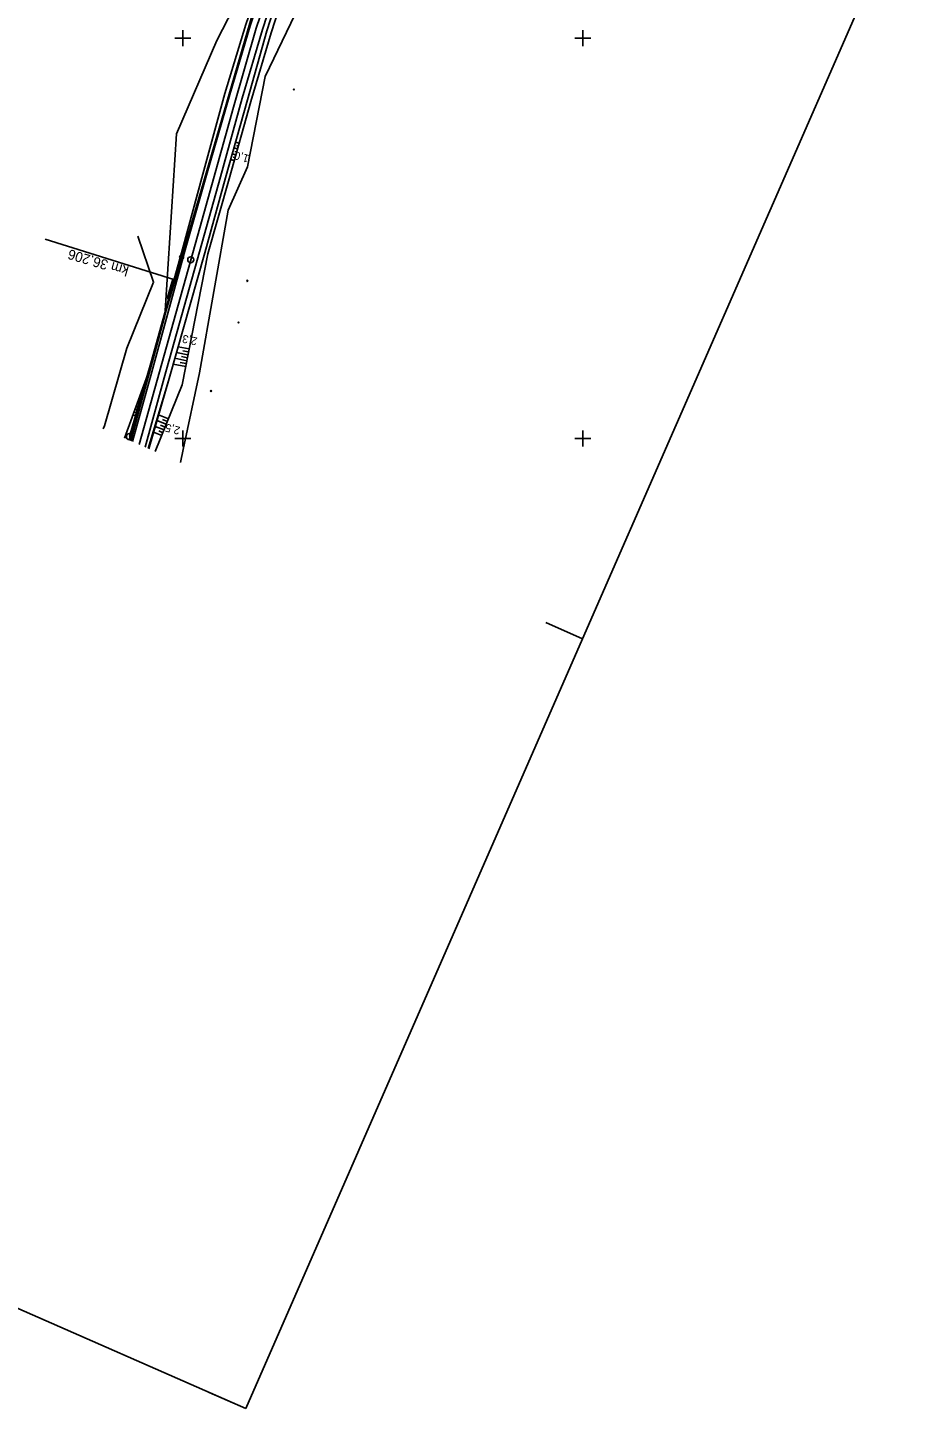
# Model space of a CAD drawing. Extents: x -806856 to -806332, y -1151642 to -1150946.
# Drawn here: x -806638.8 to -806415.8, y -1151642.4 to -1151297.3 of the extents above; entities that cross this region are included whole.
import ezdxf

# ---------------------------------------------------------------- set-up
doc = ezdxf.new("R2010")
doc.units = 0
for name, color, linetype in [('0381KM032-037P - Vrstva 1', 7, 'Continuous'), ('0381KM032-037P - Vrstva 17', 7, 'Continuous'), ('0381KM032-037P - Vrstva 4', 7, 'Continuous'), ('0381KM032-037P - Vrstva 48', 7, 'Continuous'), ('0381KM032-037P - Vrstva 49', 7, 'Continuous'), ('0381KM032-037P - Vrstva 7', 7, 'Continuous'), ('0381KM032-037P - Vrstva 9', 7, 'Continuous'), ('formát', 7, 'Continuous'), ('hran DP - hran DP', 7, 'Continuous'), ('krizky_1000 - Vrstva 1', 7, 'Continuous'), ('vyt_sit - polygon', 7, 'Continuous'), ('vyt_sit - stávající', 7, 'Continuous')]:
    doc.layers.add(name, color=color, linetype=linetype)

msp = doc.modelspace()

# ---------------------------------------------------------------- linework, layer by layer
at = {"layer": '0381KM032-037P - Vrstva 1'}
for points in [[(-806575.26, -1151278.66), (-806581.61, -1151297.45), (-806587.32, -1151317.2)], [(-806587.32, -1151317.2), (-806595.77, -1151347.36), (-806604.1, -1151377.15), (-806610.94, -1151401.52)]]:
    msp.add_lwpolyline(points, dxfattribs=at)
at = {"layer": '0381KM032-037P - Vrstva 17'}
msp.add_lwpolyline([(-806611.24, -1151349.41), (-806607.31, -1151360.99), (-806614.01, -1151377.45), (-806619.53, -1151396.86), (-806619.89, -1151397.6)], dxfattribs=at)
at = {"layer": '0381KM032-037P - Vrstva 4'}
for points in [[(-806534.73, -1151198.81), (-806545.37, -1151216.39), (-806553.18, -1151229.13), (-806561.58, -1151243.53), (-806567.96, -1151255.6), (-806574.3, -1151269.24), (-806578.76, -1151280.27), (-806579.4, -1151282.54), (-806584.22, -1151296.56), (-806589.48, -1151313.82), (-806594.95, -1151333.92), (-806600.1, -1151352.67), (-806608.81, -1151384.22), (-806613.08, -1151400.58)], [(-806534.14, -1151199.19), (-806544.55, -1151216.75), (-806552.31, -1151229.7), (-806560.71, -1151244.03), (-806567.24, -1151256.24), (-806573.52, -1151269.73), (-806577.97, -1151280.92), (-806578.5, -1151282.67), (-806583.15, -1151296.86), (-806588.26, -1151314.07), (-806594.08, -1151334.22), (-806599.38, -1151352.89), (-806608.02, -1151384.26), (-806612.6, -1151400.79)], [(-806531.11, -1151200.55), (-806541.48, -1151217.8), (-806549.08, -1151230.92), (-806557.69, -1151245.47), (-806564.05, -1151257.36), (-806570.21, -1151270.63), (-806574.62, -1151281.75), (-806575.45, -1151283.67), (-806580.1, -1151297.77), (-806585.12, -1151314.97), (-806590.56, -1151334.63), (-806595.8, -1151353.37), (-806604.61, -1151384.9), (-806609.41, -1151402.19)], [(-806530.22, -1151201.05), (-806540.66, -1151218.65), (-806548.31, -1151231.35), (-806556.78, -1151246.08), (-806563.07, -1151257.89), (-806569.22, -1151271.02), (-806574.1, -1151282.08), (-806574.48, -1151284.1), (-806578.97, -1151298.16), (-806583.83, -1151315.38), (-806589.34, -1151334.88), (-806594.45, -1151353.63), (-806603.42, -1151385.04), (-806608.69, -1151402.5)]]:
    msp.add_lwpolyline(points, dxfattribs=at)
at = {"layer": '0381KM032-037P - Vrstva 48'}
for p, q in [((-806585.91, -1151326.21), (-806586.82, -1151325.96)), ((-806586.11, -1151326.94), (-806586.57, -1151326.81)), ((-806587.11, -1151330.55), (-806588.04, -1151330.29)), ((-806586.71, -1151329.1), (-806587.63, -1151328.85)), ((-806586.91, -1151329.82), (-806587.38, -1151329.7)), ((-806586.31, -1151327.66), (-806587.23, -1151327.4)), ((-806586.51, -1151328.38), (-806586.97, -1151328.25)), ((-806598.69, -1151379.1), (-806601.56, -1151378.53)), ((-806598.39, -1151377.63), (-806601.15, -1151377.08)), ((-806598.54, -1151378.36), (-806599.95, -1151378.08)), ((-806599.27, -1151382.04), (-806602.39, -1151381.42)), ((-806598.98, -1151380.57), (-806601.97, -1151379.98)), ((-806599.12, -1151381.31), (-806600.65, -1151381)), ((-806598.83, -1151379.83), (-806600.3, -1151379.54)), ((-806611.67, -1151391.97), (-806611.36, -1151392.08)), ((-806611.41, -1151391.27), (-806610.85, -1151391.47)), ((-806611.15, -1151390.56), (-806610.9, -1151390.65)), ((-806610.89, -1151389.86), (-806610.44, -1151390.02)), ((-806612.45, -1151394.08), (-806611.67, -1151394.37)), ((-806612.19, -1151393.38), (-806611.83, -1151393.51)), ((-806611.93, -1151392.67), (-806611.26, -1151392.92)), ((-806604.12, -1151396.48), (-806606.45, -1151395.55)), ((-806603.57, -1151395.08), (-806606.03, -1151394.1)), ((-806603.85, -1151395.78), (-806605.04, -1151395.3)), ((-806605.24, -1151399.26), (-806607.28, -1151398.45)), ((-806604.68, -1151397.87), (-806606.87, -1151397)), ((-806604.96, -1151398.57), (-806606.02, -1151398.14)), ((-806604.4, -1151397.17), (-806605.53, -1151396.72))]:
    msp.add_line(p, q, dxfattribs=at)
at = {"layer": '0381KM032-037P - Vrstva 49'}
for p, q in [((-806572.06, -1151312.59), (-806572.42, -1151312.95)), ((-806572.42, -1151312.59), (-806572.06, -1151312.95)), ((-806583.68, -1151360.44), (-806584.03, -1151360.8)), ((-806584.03, -1151360.44), (-806583.68, -1151360.8)), ((-806585.91, -1151370.83), (-806586.27, -1151371.18)), ((-806586.27, -1151370.83), (-806585.91, -1151371.18)), ((-806608.81, -1151384.22), (-806613.38, -1151400.45)), ((-806608.81, -1151384.22), (-806613.08, -1151400.58)), ((-806592.76, -1151387.98), (-806593.11, -1151388.33)), ((-806593.11, -1151387.98), (-806592.75, -1151388.33))]:
    msp.add_line(p, q, dxfattribs=at)
for points in [[(-806520.01, -1151188.39), (-806536.66, -1151214.61), (-806549.93, -1151238.4), (-806571.09, -1151278.57), (-806574.7, -1151288.79), (-806577.92, -1151298.67), (-806582.99, -1151315.77), (-806588.39, -1151335.12), (-806593.7, -1151353.88), (-806600.16, -1151386.57)], [(-806535.85, -1151198.12), (-806546.61, -1151215.57), (-806553.18, -1151229.13), (-806561.58, -1151243.53), (-806567.96, -1151255.6), (-806574.3, -1151269.24), (-806578.76, -1151280.27), (-806579.4, -1151282.54), (-806584.22, -1151296.56), (-806589.48, -1151313.82), (-806594.95, -1151333.92), (-806600.1, -1151352.67), (-806608.81, -1151384.22), (-806614.6, -1151399.91)], [(-806574.1, -1151282.08), (-806574.48, -1151284.1), (-806578.97, -1151298.16), (-806583.83, -1151315.38), (-806589.34, -1151334.88), (-806594.45, -1151353.63), (-806603.42, -1151385.04), (-806608.48, -1151402.59)], [(-806608.69, -1151402.5), (-806603.42, -1151385.04)], [(-806600.16, -1151386.57), (-806606.86, -1151403.3)]]:
    msp.add_lwpolyline(points, dxfattribs=at)
at = {"layer": '0381KM032-037P - Vrstva 7'}
msp.add_line((-806600.34, -1151354.71), (-806600.24, -1151354.71), dxfattribs=at)
for centre, radius in [((-806600.29, -1151354.71), 0.5), ((-806598, -1151355.35), 0.75)]:
    msp.add_circle(centre, radius, dxfattribs=at)
at = {"layer": '0381KM032-037P - Vrstva 9'}
for p, q in [((-806602.2, -1151360.29), (-806634.39, -1151350.17)), ((-806602.49, -1151360.21), (-806603.91, -1151365)), ((-806603.33, -1151365.17), (-806601.91, -1151360.38)), ((-806602.49, -1151360.21), (-806603.06, -1151360.04)), ((-806601.91, -1151360.38), (-806602.49, -1151360.21)), ((-806603.91, -1151365), (-806603.33, -1151365.17))]:
    msp.add_line(p, q, dxfattribs=at)
at = {"layer": 'formát'}
for p, q in [((-806415.83, -1151257.68), (-806500.03, -1151450.06)), ((-806509.19, -1151446.05), (-806500.03, -1151450.06)), ((-806509.19, -1151446.05), (-806500.03, -1151450.06)), ((-806500.03, -1151450.06), (-806584.22, -1151642.44)), ((-806856.31, -1151523.36), (-806584.22, -1151642.44)), ((-806593.38, -1151638.43), (-806584.22, -1151642.44))]:
    msp.add_line(p, q, dxfattribs=at)
at = {"layer": 'hran DP - hran DP'}
for p, q in [((-806591.51, -1151300.57), (-806576.79, -1151271.69)), ((-806561.98, -1151273.31), (-806579.39, -1151309.52)), ((-806601.55, -1151323.84), (-806591.51, -1151300.57)), ((-806579.39, -1151309.52), (-806583.8, -1151332.16)), ((-806604.52, -1151369.36), (-806601.55, -1151323.84)), ((-806583.8, -1151332.16), (-806588.67, -1151342.95)), ((-806588.67, -1151342.95), (-806595.8, -1151383.59)), ((-806612.97, -1151400.63), (-806604.52, -1151369.36)), ((-806595.8, -1151383.59), (-806599.86, -1151402.77)), ((-806599.86, -1151402.77), (-806600.56, -1151406.06))]:
    msp.add_line(p, q, dxfattribs=at)
at = {"layer": 'krizky_1000 - Vrstva 1'}
for points in [[(-806600, -1151298), (-806600, -1151302)], [(-806500, -1151298), (-806500, -1151302)], [(-806602, -1151300), (-806598, -1151300)], [(-806502, -1151300), (-806498, -1151300)], [(-806600, -1151398), (-806600, -1151402)], [(-806500, -1151398), (-806500, -1151402)], [(-806602, -1151400), (-806598, -1151400)], [(-806502, -1151400), (-806498, -1151400)]]:
    msp.add_lwpolyline(points, dxfattribs=at)
at = {"layer": 'vyt_sit - polygon'}
msp.add_line((-806613.33, -1151399.56), (-806578.17, -1151278.81), dxfattribs=at)
at = {"layer": 'vyt_sit - stávající'}
msp.add_line((-806613.39, -1151399.56), (-806613.29, -1151399.56), dxfattribs=at)
msp.add_circle((-806613.33, -1151399.56), 0.756, dxfattribs=at)

# ---------------------------------------------------------------- texts
at = {"layer": '0381KM032-037P - Vrstva 48'}
for s, rotation, p in [('1,0', 164.2247, (-806583.24, -1151329.23)), ('2,3', 167.817, (-806596.23, -1151374.85)), ('2,5', 166.3296, (-806600.51, -1151397.17))]:
    msp.add_text(s, height=2, rotation=rotation, dxfattribs=at).set_placement(p)
at = {"layer": '0381KM032-037P - Vrstva 9'}
msp.add_text('km 36,206', height=2.5, rotation=163.5076, dxfattribs=at).set_placement((-806613.29, -1151357.1))

doc.saveas('drawing.dxf')
